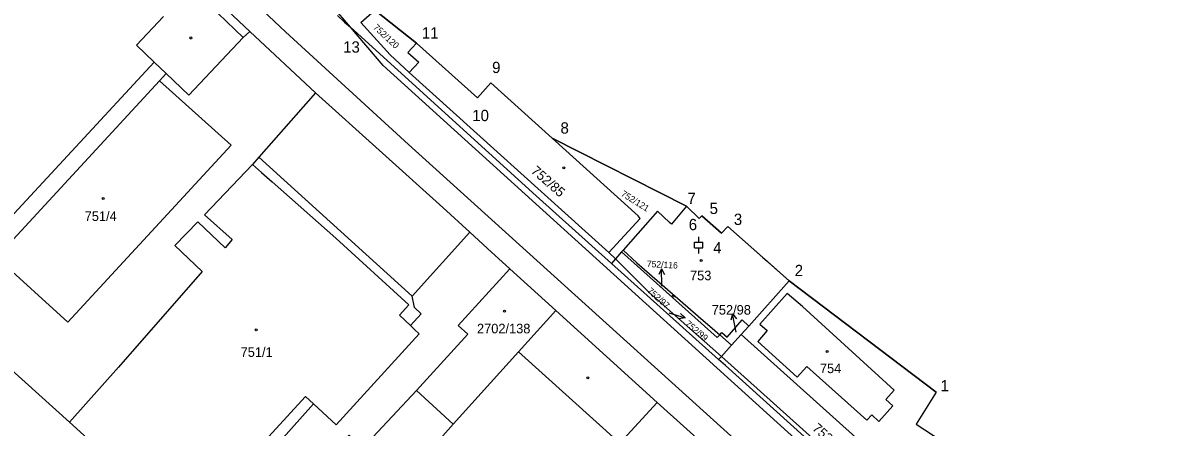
# Model space of a CAD drawing. Extents: x -496682 to -495907, y -1088575 to -1088018.
# Drawn here: x -496399.3 to -496196, y -1088432.3 to -1088360.6 of the extents above; entities that cross this region are included whole.
import ezdxf

# ---------------------------------------------------------------- set-up
doc = ezdxf.new("R2010")
doc.units = 0
for name, color, linetype in [('Hranice parcel', 7, 'Continuous'), ('Parcelní čísla', 7, 'Continuous'), ('Pop  PČ popisy', 7, 'Continuous'), ('Vnitřní kresba', 7, 'Continuous'), ('Vrstva 31', 7, 'Continuous'), ('Vrstva 32', 7, 'Continuous'), ('Vrstva 54', 7, 'Continuous'), ('Značky budov', 7, 'Continuous'), ('Značky kultur', 7, 'Continuous')]:
    doc.layers.add(name, color=color, linetype=linetype)

msp = doc.modelspace()

# ---------------------------------------------------------------- linework, layer by layer
at = {"layer": 'Hranice parcel'}
for p, q in [((-496347.42, -1088372.97), (-496359.06, -1088362.08)), ((-496415.13, -1088409.73), (-496376.05, -1088367.51)), ((-496295.37, -1088401.32), (-496330.83, -1088369.38)), ((-496305.46, -1088381.01), (-496281.64, -1088393.07)), ((-496294.19, -1088402.41), (-496295.37, -1088401.32)), ((-496293.12, -1088401.19), (-496294.19, -1088402.41)), ((-496292.87, -1088400.91), (-496293.12, -1088401.19)), ((-496294.19, -1088402.41), (-496294.91, -1088403.24)), ((-496275.92, -1088420.27), (-496294.91, -1088403.24)), ((-496270.58, -1088414.34), (-496263.38, -1088406.35)), ((-496286.81, -1088427.89), (-496304.81, -1088411.58)), ((-496271.94, -1088415.85), (-496270.58, -1088414.34)), ((-496273.63, -1088417.73), (-496275.71, -1088415.91)), ((-496273.63, -1088417.73), (-496271.94, -1088415.85)), ((-496275.42, -1088419.72), (-496273.63, -1088417.73)), ((-496275.92, -1088420.27), (-496275.42, -1088419.72)), ((-496235.01, -1088455.98), (-496275.42, -1088419.72)), ((-496329.51, -1088425.77), (-496322.98, -1088431.74)), ((-496270.9, -1088442.22), (-496286.81, -1088427.89)), ((-496322.98, -1088431.74), (-496349.17, -1088461.01))]:
    msp.add_line(p, q, dxfattribs=at)
for points in [[(-496248.09, -1088462.93), (-496246.94, -1088461.48), (-496246.55, -1088459.79), (-496247.27, -1088457.92), (-496249.13, -1088456.06), (-496330.94, -1088382.16), (-496352.76, -1088362.17), (-496394.53, -1088322.76)], [(-496359.06, -1088362.08), (-496374.12, -1088347.89), (-496379.4, -1088342.98), (-496392.05, -1088330.77)], [(-496341.24, -1088361.35), (-496344.49, -1088357.55), (-496352.49, -1088347.86)], [(-496339.41, -1088360.51), (-496336.89, -1088358.33), (-496329.48, -1088364.15)], [(-496343.5, -1088359.28), (-496342.26, -1088360.42), (-496341.24, -1088361.35)], [(-496330.83, -1088369.38), (-496334.19, -1088366.23), (-496339.41, -1088360.51)], [(-496376.05, -1088367.51), (-496373.92, -1088369.56), (-496369.92, -1088373.4), (-496360.24, -1088363.14), (-496359.06, -1088362.08)], [(-496294.91, -1088403.24), (-496308.3, -1088391.23), (-496341.24, -1088361.35)], [(-496113.2, -1088569.45), (-496126.78, -1088557.15), (-496235.31, -1088458.83), (-496335.43, -1088368.13), (-496341.24, -1088361.35)], [(-496329.48, -1088364.15), (-496331.02, -1088365.83), (-496329.12, -1088367.54), (-496330.83, -1088369.38)], [(-496329.48, -1088364.15), (-496318.71, -1088373.85), (-496316.3, -1088371.21), (-496305.46, -1088381.01)], [(-496347.42, -1088372.97), (-496357.46, -1088384.36), (-496358.63, -1088385.68), (-496367.13, -1088394.6), (-496362.2, -1088399), (-496363.47, -1088400.45), (-496368.31, -1088395.83), (-496372.35, -1088400.06), (-496367.51, -1088404.68)], [(-496320.05, -1088397.68), (-496324.85, -1088393.33), (-496347.42, -1088372.97)], [(-496295.37, -1088401.32), (-496289.83, -1088395.26), (-496290.2, -1088394.8), (-496305.46, -1088381.01)], [(-496281.64, -1088393.07), (-496284.3, -1088396.25), (-496284.64, -1088395.96), (-496286.75, -1088393.98), (-496292.87, -1088400.91)], [(-496281.64, -1088393.07), (-496279.37, -1088395.26), (-496278.92, -1088394.77), (-496275.4, -1088397.89), (-496274.28, -1088396.67), (-496268.16, -1088402.12), (-496267.26, -1088402.88), (-496263.38, -1088406.35)], [(-496353.62, -1088434.72), (-496347.79, -1088428.16), (-496343.74, -1088431.85), (-496329.03, -1088415.71), (-496329.94, -1088414.89), (-496330.57, -1088414.27), (-496328.66, -1088412.18), (-496329.87, -1088411.04), (-496330.29, -1088409.02), (-496320.05, -1088397.68)], [(-496320.05, -1088397.68), (-496316.9, -1088400.57), (-496312.96, -1088404.2), (-496304.81, -1088411.58)], [(-496275.71, -1088415.91), (-496276.17, -1088416.39), (-496293.12, -1088401.19)], [(-496292.87, -1088400.91), (-496290.41, -1088403.13), (-496278.64, -1088413.37), (-496277.5, -1088414.34), (-496275.71, -1088415.91)], [(-496294.19, -1088402.41), (-496288.2, -1088408.47), (-496275.42, -1088419.72)], [(-496367.51, -1088404.68), (-496382.38, -1088421.63), (-496391.09, -1088431.4)], [(-496263.38, -1088406.35), (-496237.32, -1088426.06), (-496240.89, -1088431.73), (-496222.1, -1088444.04), (-496214.16, -1088448.81), (-496203.17, -1088456.69), (-496183.01, -1088473.86)], [(-496247.48, -1088431.25), (-496245.02, -1088428.51), (-496246.28, -1088427.38), (-496244.75, -1088425.7), (-496261.03, -1088410.9), (-496263.76, -1088408.58), (-496268.63, -1088414.01), (-496267.32, -1088415.15), (-496268.99, -1088417.07), (-496262.01, -1088423.42), (-496260.29, -1088421.52), (-496249.6, -1088431.03), (-496248.76, -1088430.1), (-496247.48, -1088431.25)], [(-496415.13, -1088409.73), (-496412.88, -1088411.76), (-496391.09, -1088431.4)], [(-496304.81, -1088411.58), (-496311.39, -1088418.91), (-496322.98, -1088431.74)], [(-496275.71, -1088415.91), (-496275.33, -1088415.51), (-496274.41, -1088416.29), (-496271.73, -1088413.23), (-496270.58, -1088414.34)], [(-496235.01, -1088455.98), (-496231.8, -1088451.84), (-496271.94, -1088415.85)], [(-496111.32, -1088569.45), (-496125.77, -1088556.38), (-496187.85, -1088499.89), (-496224.3, -1088466.84), (-496274.7, -1088421.37), (-496275.92, -1088420.27)], [(-496353.62, -1088434.72), (-496344.49, -1088436.33), (-496341.48, -1088433.73), (-496338.95, -1088435.92), (-496329.51, -1088425.77)], [(-496286.81, -1088427.89), (-496293.46, -1088435.15), (-496314.33, -1088457.95)], [(-496391.09, -1088431.4), (-496372.42, -1088448.31), (-496368.72, -1088451.67)]]:
    msp.add_lwpolyline(points, dxfattribs=at)
at = {"layer": 'Pop  PČ popisy'}
for p, q in [((-496286.05, -1088404.19), (-496286.54, -1088405.2)), ((-496286, -1088407.19), (-496286.05, -1088404.19)), ((-496286.05, -1088404.19), (-496285.53, -1088405.18)), ((-496285.99, -1088407.3), (-496286, -1088407.19)), ((-496284.72, -1088412.02), (-496281.85, -1088412.9)), ((-496281.85, -1088412.9), (-496282.95, -1088413.08)), ((-496281.85, -1088412.9), (-496282.66, -1088412.13)), ((-496273.46, -1088412.2), (-496273.75, -1088413.28)), ((-496272.84, -1088415.13), (-496273.46, -1088412.2)), ((-496273.46, -1088412.2), (-496272.77, -1088413.07)), ((-496272.78, -1088415.41), (-496272.84, -1088415.13))]:
    msp.add_line(p, q, dxfattribs=at)
at = {"layer": 'Vnitřní kresba'}
for p, q in [((-496372.36, -1088351.5), (-496360.24, -1088363.14)), ((-496379.15, -1088364.54), (-496374.38, -1088359.45)), ((-496376.05, -1088367.51), (-496379.15, -1088364.54)), ((-496404.03, -1088402.17), (-496375.12, -1088370.85)), ((-496373.92, -1088369.56), (-496375.12, -1088370.85)), ((-496375.12, -1088370.85), (-496362.41, -1088382.27)), ((-496362.41, -1088382.27), (-496391.38, -1088413.68)), ((-496357.46, -1088384.36), (-496330.29, -1088409.02)), ((-496358.63, -1088385.68), (-496356.99, -1088387.12)), ((-496356.99, -1088387.12), (-496355.14, -1088388.75)), ((-496355.14, -1088388.75), (-496343.81, -1088398.74)), ((-496391.38, -1088413.68), (-496404.03, -1088402.17)), ((-496312.96, -1088404.2), (-496322.1, -1088414.27)), ((-496322.1, -1088414.27), (-496320.41, -1088415.8)), ((-496320.41, -1088415.8), (-496329.51, -1088425.77)), ((-496293.46, -1088435.15), (-496311.39, -1088418.91)), ((-496362, -1088440.78), (-496349.22, -1088426.85)), ((-496349.22, -1088426.85), (-496347.79, -1088428.16))]:
    msp.add_line(p, q, dxfattribs=at)
msp.add_lwpolyline([(-496330.57, -1088414.27), (-496332.53, -1088412.43), (-496330.87, -1088410.6), (-496343.81, -1088398.74)], dxfattribs=at)
at = {"layer": 'Vrstva 31'}
for p, q in [((-496329.48, -1088364.15), (-496329.48, -1088364.15)), ((-496316.3, -1088371.21), (-496316.3, -1088371.21)), ((-496318.71, -1088373.85), (-496318.71, -1088373.85)), ((-496305.46, -1088381.01), (-496305.46, -1088381.01)), ((-496281.64, -1088393.07), (-496281.64, -1088393.07)), ((-496279.37, -1088395.26), (-496279.37, -1088395.26)), ((-496278.92, -1088394.77), (-496278.92, -1088394.77)), ((-496274.28, -1088396.67), (-496274.28, -1088396.67)), ((-496275.4, -1088397.89), (-496275.4, -1088397.89)), ((-496263.38, -1088406.35), (-496263.38, -1088406.35)), ((-496237.32, -1088426.06), (-496237.32, -1088426.06))]:
    msp.add_line(p, q, dxfattribs=at)
at = {"layer": 'Vrstva 54'}
msp.add_lwpolyline([(-496237.32, -1088426.06), (-496263.38, -1088406.35), (-496274.28, -1088396.67), (-496275.4, -1088397.89), (-496278.92, -1088394.77), (-496279.37, -1088395.26), (-496281.64, -1088393.07), (-496305.46, -1088381.01), (-496316.3, -1088371.21), (-496318.71, -1088373.85), (-496329.48, -1088364.15), (-496336.89, -1088358.33)], dxfattribs=at)
at = {"layer": 'Značky budov'}
for centre in [(-496369.52, -1088363.24), (-496303.39, -1088386.28), (-496385.1, -1088391.74), (-496278.99, -1088402.7), (-496283.96, -1088409.03), (-496313.92, -1088411.69), (-496357.95, -1088415.03), (-496256.64, -1088418.87), (-496299.1, -1088423.51)]:
    msp.add_circle(centre, 0.175, dxfattribs=at)
at = {"layer": 'Značky kultur'}
for p, q in [((-496279.44, -1088399.49), (-496279.44, -1088398.49)), ((-496280.19, -1088399.49), (-496278.69, -1088399.49)), ((-496280.19, -1088400.49), (-496280.19, -1088399.49)), ((-496280.19, -1088400.49), (-496278.69, -1088400.49)), ((-496279.44, -1088401.49), (-496279.44, -1088400.49)), ((-496278.69, -1088400.49), (-496278.69, -1088399.49))]:
    msp.add_line(p, q, dxfattribs=at)

# ---------------------------------------------------------------- texts
at = {"layer": 'Parcelní čísla'}
for s, height, rotation, p in [('752/120', 1.139, 317, (-496337.28, -1088361.49)), ('752/85', 1.7, 319, (-496309.32, -1088387.03)), ('752/121', 1.139, 328, (-496293.35, -1088391.18)), ('752/116', 1.139, 357, (-496288.68, -1088403.87)), ('752/97', 1.139, 318, (-496288.68, -1088408.24)), ('752/99', 1.139, 320, (-496281.95, -1088414.12)), ('752/111', 1.7, 318, (-496259.43, -1088432.66))]:
    msp.add_text(s, height=height, rotation=rotation, dxfattribs=at).set_placement(p)
for s, p in [('751/4', (-496388.37, -1088395.7)), ('753', (-496280.99, -1088406.22)), ('752/98', (-496277.14, -1088412.32)), ('2702/138', (-496318.78, -1088415.64)), ('751/1', (-496360.71, -1088419.82)), ('754', (-496257.95, -1088422.7))]:
    msp.add_text(s, height=1.7, dxfattribs=at).set_placement(p)
at = {"layer": 'Vrstva 32'}
for s, p in [('11', (-496328.57, -1088363.34)), ('13', (-496342.53, -1088365.84)), ('9', (-496316.1, -1088369.46)), ('10', (-496319.63, -1088377.99)), ('8', (-496303.97, -1088380.2)), ('7', (-496281.45, -1088392.69)), ('5', (-496277.52, -1088394.47)), ('3', (-496273.22, -1088396.41)), ('6', (-496281.22, -1088397.34)), ('4', (-496276.88, -1088401.46)), ('2', (-496262.42, -1088405.49)), ('1', (-496236.53, -1088425.91))]:
    msp.add_text(s, height=2, dxfattribs=at).set_placement(p)

doc.saveas('drawing.dxf')
